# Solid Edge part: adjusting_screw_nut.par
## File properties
Title: Adjusting screw nut
Author: Deepak Maini
Template: Normal.par
Last saved by: CADCIM
Revision: 7
Application: Solid Edge
Accuracy: 0.99
Material: aluminum
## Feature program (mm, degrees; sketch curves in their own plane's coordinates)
sketch for "unnamed RevolvedProtrusion 1" plane through (0, 0, 0) normal (0, -1, 0) x-axis (1, 0, 0)
  line (25.4, 9.7462) -> (74.676, 9.7462)
  line (76.2, 8.2222) -> (74.676, 9.7462)
  line (76.2, -26.8298) -> (76.2, 8.2222)
  line (76.2, -26.8298) -> (74.676, -28.3538)
  line (74.676, -28.3538) -> (47.625, -28.3538)
  line (47.625, -28.3538) -> (47.625, -60.1038)
  line (47.625, -60.1038) -> (25.4, -60.1038)
  line (25.4, -60.1038) -> (25.4, 9.7462)
revolve "unnamed RevolvedProtrusion 1" add full turn 360 deg
sketch for "Hole_1" plane through (76.2, 0, 0) normal (1, 0, 0) x-axis (0, 1, 0)
  hole centre (0, -9.3038) bore radius 9.5123
hole "Hole_1" diameter 19.0246 finite  VBottomAngle = 118 deg
pattern "unnamed Pattern 1" of "Hole_1"
pattern "unnamed Pattern 2"
sketch for "unnamed Cutout 1" plane through (0, 0, 9.7462) normal (0, 0, 1) x-axis (1, 0, 0)
extrude "unnamed Cutout 1" cut through along -normal
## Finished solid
Body 1: solid body, 16 faces, 16 edges, 4 vertices.
  Faces by surface: cylinder 7, cone 6, plane 3
  Edges by curve: circle 12, intersection 4
Bounding box of the edges (mm): 152.400 x 152.400 x 69.850, from (-76.2, -76.2, -60.1038) to (76.2, 76.2, 9.7462).
Cylindrical faces by radius (mm): R9.5123 x4, R38.1 x1, R47.625 x1, R76.2 x1
Conical faces (half-angle, radius in mm at the cone's reference point): 45 deg R74.676 x1, 45 deg R76.2 x1, 59 deg R9.5123 x4
Planar faces by outward normal: +z 1, -z 2
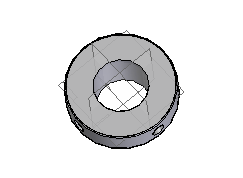
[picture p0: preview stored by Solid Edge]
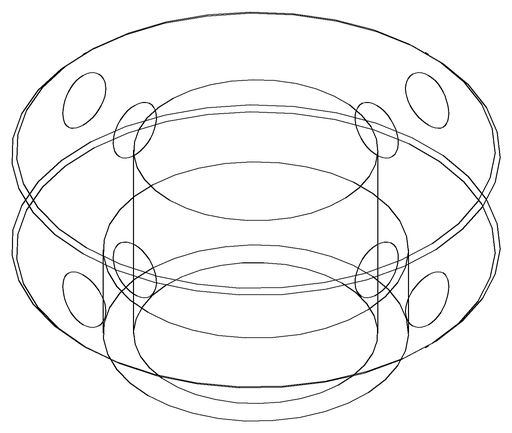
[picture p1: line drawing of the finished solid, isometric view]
